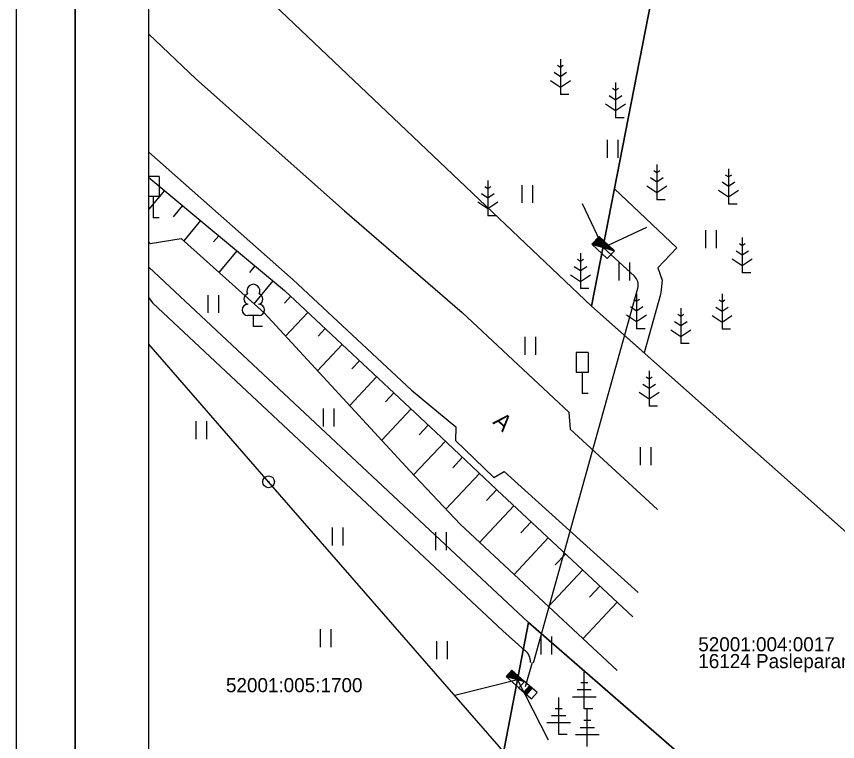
# Model space of a CAD drawing. Extents: x 469361.3 to 469413.8, y 6542171.3 to 6542245.5.
# Drawn here: x 469361.27 to 469396.16, y 6542186.8 to 6542217.59 of the extents above; entities that cross this region are included whole.
import ezdxf

# ---------------------------------------------------------------- set-up
doc = ezdxf.new("R2010")
doc.units = 0
for name, color, linetype in [('HALJASTUS', 7, 'Continuous'), ('Hepta_tarbijatoru', 7, 'Continuous'), ('KASUTUSALA', 7, 'Continuous'), ('KPOHULIIN', 7, 'Continuous'), ('LIIKLUS', 7, 'Continuous'), ('MADALPINGE', 7, 'Continuous'), ('PIIR', 7, 'Continuous'), ('POST', 7, 'Continuous'), ('PUU', 7, 'Continuous'), ('RELJEEF', 7, 'Continuous'), ('TEE', 7, 'Continuous'), ('VORMISTUS', 7, 'Continuous')]:
    doc.layers.add(name, color=color, linetype=linetype)

msp = doc.modelspace()

# ---------------------------------------------------------------- linework, layer by layer
at = {"layer": 'HALJASTUS'}
for p, q in [((469386.366, 6542212.352), (469386.366, 6542211.591)), ((469386.821, 6542212.352), (469386.821, 6542211.591)), ((469382.742, 6542210.432), (469382.742, 6542209.671)), ((469383.197, 6542210.432), (469383.197, 6542209.671)), ((469390.544, 6542208.512), (469390.544, 6542207.751)), ((469390.999, 6542208.512), (469390.999, 6542207.751)), ((469386.863, 6542207.147), (469386.863, 6542206.386)), ((469387.318, 6542207.147), (469387.318, 6542206.386)), ((469369.398, 6542205.761), (469369.398, 6542205)), ((469369.853, 6542205.761), (469369.853, 6542205)), ((469382.87, 6542203.99), (469382.87, 6542203.229)), ((469383.325, 6542203.99), (469383.325, 6542203.229)), ((469374.301, 6542200.94), (469374.301, 6542200.179)), ((469374.756, 6542200.94), (469374.756, 6542200.179)), ((469368.886, 6542200.407), (469368.886, 6542199.646)), ((469369.341, 6542200.407), (469369.341, 6542199.646)), ((469387.773, 6542199.298), (469387.773, 6542198.537)), ((469388.228, 6542199.298), (469388.228, 6542198.537)), ((469374.685, 6542195.885), (469374.685, 6542195.124)), ((469375.14, 6542195.885), (469375.14, 6542195.124)), ((469379.076, 6542195.693), (469379.076, 6542194.932)), ((469379.531, 6542195.693), (469379.531, 6542194.932)), ((469374.173, 6542191.577), (469374.173, 6542190.815)), ((469374.628, 6542191.577), (469374.628, 6542190.815)), ((469383.552, 6542191.257), (469383.552, 6542190.495)), ((469384.007, 6542191.257), (469384.007, 6542190.495)), ((469379.118, 6542191.065), (469379.118, 6542190.304)), ((469379.573, 6542191.065), (469379.573, 6542190.304))]:
    msp.add_line(p, q, dxfattribs=at)
at = {"layer": 'Hepta_tarbijatoru'}
for points in [[(469386.196, 6542207.779), (469385.314, 6542209.631)], [(469386.196, 6542207.779), (469388.057, 6542208.638)], [(469382.553, 6542189.429), (469379.901, 6542188.753)], [(469382.553, 6542189.429), (469383.86, 6542186.881)]]:
    msp.add_lwpolyline(points, dxfattribs=at)
at = {"layer": 'KASUTUSALA'}
msp.add_lwpolyline([(469389.323, 6542207.768), (469388.517, 6542206.919), (469388.699, 6542206.389), (469388.67, 6542205.987), (469388.67, 6542205.985), (469388.67, 6542205.984), (469388.653, 6542205.889), (469388.637, 6542205.794), (469388.636, 6542205.792), (469388.636, 6542205.791), (469387.945, 6542203.307), (469385.71, 6542205.29), (469386.684, 6542210.273)], close=True, dxfattribs=at)
at = {"layer": 'KPOHULIIN'}
msp.add_lwpolyline([(469387.064, 6542180.54), (469371.981, 6542197.833), (469366.891, 6542203.679)], dxfattribs=at)
at = {"layer": 'LIIKLUS'}
for p, q in [((469367.326, 6542210.794), (469366.891, 6542210.794)), ((469367.326, 6542210.794), (469367.326, 6542209.944)), ((469367.326, 6542209.944), (469366.891, 6542209.944)), ((469367.076, 6542209.944), (469367.076, 6542209.044)), ((469367.326, 6542209.044), (469367.076, 6542209.044)), ((469385.055, 6542203.325), (469385.055, 6542202.475)), ((469385.555, 6542203.325), (469385.055, 6542203.325)), ((469385.555, 6542203.325), (469385.555, 6542202.475)), ((469385.555, 6542202.475), (469385.055, 6542202.475)), ((469385.305, 6542202.475), (469385.305, 6542201.575)), ((469385.555, 6542201.575), (469385.305, 6542201.575))]:
    msp.add_line(p, q, dxfattribs=at)
at = {"layer": 'MADALPINGE'}
for p, q in [((469386.024, 6542208.25), (469385.716, 6542207.924)), ((469385.716, 6542207.924), (469386.369, 6542207.307)), ((469385.716, 6542207.924), (469386.677, 6542207.633)), ((469385.727, 6542207.921), (469385.72, 6542207.928)), ((469385.754, 6542207.913), (469385.728, 6542207.937)), ((469385.781, 6542207.904), (469385.737, 6542207.946)), ((469385.808, 6542207.896), (469385.746, 6542207.955)), ((469385.836, 6542207.888), (469385.754, 6542207.965)), ((469385.863, 6542207.88), (469385.763, 6542207.974)), ((469385.89, 6542207.872), (469385.772, 6542207.983)), ((469385.917, 6542207.863), (469385.781, 6542207.992)), ((469385.944, 6542207.855), (469385.789, 6542208.001)), ((469385.971, 6542207.847), (469385.798, 6542208.011)), ((469385.998, 6542207.839), (469385.807, 6542208.02)), ((469386.026, 6542207.83), (469385.815, 6542208.029)), ((469386.053, 6542207.822), (469385.824, 6542208.038)), ((469386.08, 6542207.814), (469385.833, 6542208.047)), ((469386.107, 6542207.806), (469385.841, 6542208.057)), ((469386.134, 6542207.798), (469385.85, 6542208.066)), ((469386.161, 6542207.789), (469385.859, 6542208.075)), ((469386.188, 6542207.781), (469385.868, 6542208.084)), ((469386.216, 6542207.773), (469385.876, 6542208.094)), ((469386.243, 6542207.765), (469385.885, 6542208.103)), ((469386.27, 6542207.757), (469385.894, 6542208.112)), ((469386.297, 6542207.748), (469385.902, 6542208.121)), ((469386.324, 6542207.74), (469385.911, 6542208.13)), ((469386.351, 6542207.732), (469385.92, 6542208.14)), ((469386.378, 6542207.724), (469385.928, 6542208.149)), ((469386.405, 6542207.716), (469385.937, 6542208.158)), ((469386.433, 6542207.707), (469385.946, 6542208.167)), ((469386.46, 6542207.699), (469385.955, 6542208.176)), ((469386.487, 6542207.691), (469385.963, 6542208.186)), ((469386.514, 6542207.683), (469385.972, 6542208.195)), ((469386.541, 6542207.675), (469385.981, 6542208.204)), ((469386.568, 6542207.666), (469385.989, 6542208.213)), ((469386.595, 6542207.658), (469385.998, 6542208.223)), ((469386.623, 6542207.65), (469386.007, 6542208.232)), ((469386.65, 6542207.642), (469386.016, 6542208.241)), ((469386.677, 6542207.633), (469386.024, 6542208.25)), ((469386.369, 6542207.307), (469386.677, 6542207.633)), ((469382.317, 6542189.829), (469382.081, 6542189.561)), ((469382.724, 6542189.39), (469382.277, 6542189.784)), ((469382.746, 6542189.385), (469382.284, 6542189.791)), ((469382.768, 6542189.379), (469382.29, 6542189.799)), ((469382.79, 6542189.373), (469382.297, 6542189.807)), ((469382.811, 6542189.367), (469382.304, 6542189.814)), ((469382.833, 6542189.362), (469382.311, 6542189.822)), ((469382.855, 6542189.356), (469382.317, 6542189.829)), ((469382.081, 6542189.561), (469382.619, 6542189.087)), ((469382.081, 6542189.561), (469382.855, 6542189.356)), ((469382.089, 6542189.558), (469382.083, 6542189.564)), ((469382.111, 6542189.552), (469382.09, 6542189.571)), ((469382.133, 6542189.547), (469382.097, 6542189.579)), ((469382.155, 6542189.541), (469382.103, 6542189.586)), ((469382.177, 6542189.535), (469382.11, 6542189.594)), ((469382.199, 6542189.529), (469382.117, 6542189.602)), ((469382.221, 6542189.524), (469382.123, 6542189.609)), ((469382.243, 6542189.518), (469382.13, 6542189.617)), ((469382.264, 6542189.512), (469382.137, 6542189.624)), ((469382.286, 6542189.506), (469382.143, 6542189.632)), ((469382.308, 6542189.5), (469382.15, 6542189.64)), ((469382.33, 6542189.495), (469382.157, 6542189.647)), ((469382.352, 6542189.489), (469382.163, 6542189.655)), ((469382.374, 6542189.483), (469382.17, 6542189.662)), ((469382.396, 6542189.477), (469382.177, 6542189.67)), ((469382.418, 6542189.471), (469382.184, 6542189.678)), ((469382.439, 6542189.466), (469382.19, 6542189.685)), ((469382.461, 6542189.46), (469382.197, 6542189.693)), ((469382.483, 6542189.454), (469382.204, 6542189.7)), ((469382.505, 6542189.448), (469382.21, 6542189.708)), ((469382.527, 6542189.443), (469382.217, 6542189.715)), ((469382.549, 6542189.437), (469382.224, 6542189.723)), ((469382.571, 6542189.431), (469382.23, 6542189.731)), ((469382.593, 6542189.425), (469382.237, 6542189.738)), ((469382.615, 6542189.419), (469382.244, 6542189.746)), ((469382.636, 6542189.414), (469382.25, 6542189.753)), ((469382.658, 6542189.408), (469382.257, 6542189.761)), ((469382.68, 6542189.402), (469382.264, 6542189.769)), ((469382.702, 6542189.396), (469382.27, 6542189.776)), ((469382.855, 6542189.356), (469382.619, 6542189.087)), ((469382.619, 6542189.087), (469382.855, 6542189.356)), ((469382.619, 6542189.087), (469383.157, 6542188.613)), ((469382.826, 6542188.904), (469383.063, 6542189.173)), ((469383.393, 6542188.882), (469382.855, 6542189.356)), ((469382.985, 6542189.084), (469383.107, 6542188.976)), ((469382.991, 6542189.091), (469383.113, 6542188.983)), ((469382.995, 6542189.096), (469383.118, 6542188.988)), ((469383.001, 6542189.103), (469383.124, 6542188.995)), ((469383.007, 6542189.109), (469383.13, 6542189.002)), ((469383.013, 6542189.116), (469383.135, 6542189.009)), ((469383.018, 6542189.122), (469383.14, 6542189.014)), ((469383.024, 6542189.128), (469383.146, 6542189.021)), ((469383.03, 6542189.135), (469383.152, 6542189.027)), ((469383.036, 6542189.142), (469383.158, 6542189.034)), ((469383.04, 6542189.147), (469383.163, 6542189.04)), ((469383.046, 6542189.154), (469383.169, 6542189.046)), ((469383.052, 6542189.161), (469383.175, 6542189.053)), ((469383.058, 6542189.167), (469383.181, 6542189.06)), ((469382.832, 6542188.911), (469382.955, 6542188.803)), ((469382.838, 6542188.917), (469382.961, 6542188.81)), ((469382.844, 6542188.924), (469382.967, 6542188.817)), ((469382.847, 6542188.927), (469382.969, 6542188.82)), ((469382.853, 6542188.934), (469382.975, 6542188.826)), ((469382.859, 6542188.941), (469382.981, 6542188.833)), ((469382.865, 6542188.948), (469382.987, 6542188.84)), ((469382.871, 6542188.954), (469382.993, 6542188.847)), ((469382.877, 6542188.961), (469382.999, 6542188.853)), ((469382.883, 6542188.968), (469383.005, 6542188.86)), ((469382.889, 6542188.975), (469383.011, 6542188.867)), ((469382.895, 6542188.981), (469383.017, 6542188.874)), ((469382.9, 6542188.988), (469383.023, 6542188.88)), ((469382.905, 6542188.993), (469383.027, 6542188.886)), ((469382.911, 6542189), (469383.033, 6542188.893)), ((469382.917, 6542189.007), (469383.039, 6542188.899)), ((469382.923, 6542189.014), (469383.045, 6542188.906)), ((469382.928, 6542189.019), (469383.05, 6542188.911)), ((469382.934, 6542189.026), (469383.056, 6542188.918)), ((469382.94, 6542189.033), (469383.062, 6542188.925)), ((469382.946, 6542189.039), (469383.068, 6542188.932)), ((469382.949, 6542188.796), (469383.185, 6542189.065)), ((469382.95, 6542189.045), (469383.073, 6542188.937)), ((469382.956, 6542189.051), (469383.079, 6542188.944)), ((469382.962, 6542189.058), (469383.084, 6542188.951)), ((469382.968, 6542189.065), (469383.09, 6542188.957)), ((469382.973, 6542189.07), (469383.095, 6542188.963)), ((469382.979, 6542189.077), (469383.101, 6542188.969)), ((469383.157, 6542188.613), (469383.393, 6542188.882))]:
    msp.add_line(p, q, dxfattribs=at)
for points in [[(469387.528, 6542206.562), (469386.196, 6542207.779)], [(469383.245, 6542190.144), (469387.673, 6542206.059)], [(469366.891, 6542205.649), (469367.055, 6542205.427), (469381.934, 6542191.507), (469382.877, 6542190.671)], [(469383.18, 6542190.157), (469382.891, 6542189.131)]]:
    msp.add_lwpolyline(points, dxfattribs=at)
for centre, radius, start, end in [((469387.191, 6542206.193), 0.5, 344.4513, 47.5946), ((469382.501, 6542190.198), 0.605, 356.4922, 51.474)]:
    msp.add_arc(centre, radius, start, end, dxfattribs=at)
at = {"layer": 'PIIR'}
for points in [[(469366.891, 6542223.149), (469385.71, 6542205.29), (469391.134, 6542233.04)], [(469391.134, 6542233.04), (469385.71, 6542205.29), (469408.141, 6542185.392)], [(469408.141, 6542185.392), (469385.71, 6542205.29), (469366.891, 6542223.149)], [(469366.891, 6542206.95), (469383.02, 6542191.86), (469396.052, 6542180.54)], [(469380.846, 6542180.54), (469383.02, 6542191.86), (469366.891, 6542206.95)], [(469396.052, 6542180.54), (469383.02, 6542191.86), (469380.846, 6542180.54)]]:
    msp.add_lwpolyline(points, dxfattribs=at)
at = {"layer": 'POST'}
for radius in [0.25, 0.0234]:
    msp.add_circle((469371.981, 6542197.833), radius, dxfattribs=at)
at = {"layer": 'PUU'}
for p, q in [((469384.38, 6542215.777), (469384.38, 6542214.277)), ((469384.38, 6542215.427), (469384.255, 6542215.51)), ((469384.504, 6542215.51), (469384.38, 6542215.427)), ((469384.38, 6542215.027), (469384.113, 6542215.205)), ((469384.647, 6542215.205), (469384.38, 6542215.027)), ((469383.956, 6542214.866), (469384.38, 6542214.583)), ((469384.38, 6542214.583), (469384.804, 6542214.866)), ((469386.726, 6542214.793), (469386.726, 6542213.293)), ((469384.74, 6542214.277), (469384.38, 6542214.277)), ((469386.726, 6542214.043), (469386.46, 6542214.221)), ((469386.726, 6542214.443), (469386.602, 6542214.526)), ((469386.851, 6542214.526), (469386.726, 6542214.443)), ((469386.993, 6542214.221), (469386.726, 6542214.043)), ((469386.302, 6542213.882), (469386.726, 6542213.599)), ((469386.726, 6542213.599), (469387.151, 6542213.882)), ((469387.086, 6542213.293), (469386.726, 6542213.293)), ((469388.476, 6542211.308), (469388.476, 6542209.808)), ((469391.527, 6542211.125), (469391.527, 6542209.625)), ((469388.476, 6542210.558), (469388.209, 6542210.736)), ((469388.476, 6542210.958), (469388.351, 6542211.041)), ((469388.6, 6542211.041), (469388.476, 6542210.958)), ((469388.742, 6542210.736), (469388.476, 6542210.558)), ((469391.527, 6542210.775), (469391.402, 6542210.858)), ((469391.651, 6542210.858), (469391.527, 6542210.775)), ((469381.297, 6542210.628), (469381.297, 6542209.128)), ((469388.051, 6542210.398), (469388.476, 6542210.115)), ((469388.476, 6542210.115), (469388.9, 6542210.398)), ((469391.527, 6542210.375), (469391.26, 6542210.552)), ((469391.793, 6542210.552), (469391.527, 6542210.375)), ((469381.297, 6542209.878), (469381.031, 6542210.056)), ((469381.297, 6542210.278), (469381.173, 6542210.361)), ((469381.422, 6542210.361), (469381.297, 6542210.278)), ((469381.564, 6542210.056), (469381.297, 6542209.878)), ((469391.103, 6542210.214), (469391.527, 6542209.931)), ((469391.527, 6542209.931), (469391.951, 6542210.214)), ((469380.873, 6542209.718), (469381.297, 6542209.435)), ((469381.297, 6542209.435), (469381.722, 6542209.718)), ((469388.836, 6542209.808), (469388.476, 6542209.808)), ((469391.887, 6542209.625), (469391.527, 6542209.625)), ((469381.657, 6542209.128), (469381.297, 6542209.128)), ((469392.111, 6542207.853), (469391.987, 6542207.936)), ((469392.111, 6542208.203), (469392.111, 6542206.703)), ((469392.236, 6542207.936), (469392.111, 6542207.853)), ((469392.111, 6542207.453), (469391.845, 6542207.631)), ((469392.378, 6542207.631), (469392.111, 6542207.453)), ((469385.232, 6542207.184), (469385.107, 6542207.267)), ((469385.232, 6542207.534), (469385.232, 6542206.034)), ((469385.356, 6542207.267), (469385.232, 6542207.184)), ((469391.687, 6542207.293), (469392.111, 6542207.01)), ((469392.111, 6542207.01), (469392.535, 6542207.293)), ((469385.232, 6542206.784), (469384.965, 6542206.962)), ((469385.498, 6542206.962), (469385.232, 6542206.784)), ((469384.807, 6542206.623), (469385.232, 6542206.34)), ((469385.232, 6542206.34), (469385.656, 6542206.623)), ((469392.471, 6542206.703), (469392.111, 6542206.703)), ((469385.592, 6542206.034), (469385.232, 6542206.034)), ((469387.62, 6542205.834), (469387.62, 6542204.334)), ((469387.62, 6542205.484), (469387.496, 6542205.567)), ((469387.745, 6542205.567), (469387.62, 6542205.484)), ((469391.249, 6542205.458), (469391.124, 6542205.541)), ((469391.249, 6542205.808), (469391.249, 6542204.308)), ((469391.373, 6542205.541), (469391.249, 6542205.458)), ((469387.62, 6542205.084), (469387.354, 6542205.262)), ((469387.887, 6542205.262), (469387.62, 6542205.084)), ((469389.497, 6542205.201), (469389.497, 6542203.701)), ((469391.249, 6542205.058), (469390.982, 6542205.236)), ((469391.515, 6542205.236), (469391.249, 6542205.058)), ((469371.576, 6542204.895), (469371.096, 6542204.895)), ((469371.336, 6542204.42), (469371.336, 6542204.895)), ((469387.196, 6542204.923), (469387.62, 6542204.641)), ((469387.62, 6542204.641), (469388.045, 6542204.923)), ((469389.497, 6542204.851), (469389.372, 6542204.934)), ((469389.621, 6542204.934), (469389.497, 6542204.851)), ((469390.824, 6542204.898), (469391.249, 6542204.615)), ((469391.249, 6542204.615), (469391.673, 6542204.898)), ((469389.497, 6542204.451), (469389.23, 6542204.628)), ((469389.763, 6542204.628), (469389.497, 6542204.451)), ((469371.716, 6542204.42), (469371.336, 6542204.42)), ((469387.98, 6542204.334), (469387.62, 6542204.334)), ((469389.072, 6542204.29), (469389.497, 6542204.007)), ((469389.497, 6542204.007), (469389.921, 6542204.29)), ((469391.609, 6542204.308), (469391.249, 6542204.308)), ((469389.857, 6542203.701), (469389.497, 6542203.701)), ((469388.153, 6542202.542), (469388.153, 6542201.042)), ((469388.153, 6542202.192), (469388.029, 6542202.275)), ((469388.278, 6542202.275), (469388.153, 6542202.192)), ((469388.153, 6542201.792), (469387.886, 6542201.969)), ((469388.42, 6542201.969), (469388.153, 6542201.792)), ((469387.729, 6542201.631), (469388.153, 6542201.348)), ((469388.153, 6542201.348), (469388.577, 6542201.631)), ((469388.513, 6542201.042), (469388.153, 6542201.042)), ((469385.395, 6542188.194), (469385.395, 6542189.769)), ((469385.545, 6542189.294), (469385.245, 6542189.294)), ((469385.695, 6542188.994), (469385.095, 6542188.994)), ((469384.308, 6542187.096), (469384.308, 6542188.671)), ((469385.895, 6542188.694), (469384.895, 6542188.694)), ((469384.458, 6542188.196), (469384.158, 6542188.196)), ((469385.755, 6542188.194), (469385.395, 6542188.194)), ((469385.525, 6542186.591), (469385.525, 6542188.166)), ((469384.608, 6542187.896), (469384.008, 6542187.896)), ((469385.675, 6542187.691), (469385.375, 6542187.691)), ((469384.808, 6542187.596), (469383.808, 6542187.596)), ((469385.825, 6542187.391), (469385.225, 6542187.391)), ((469384.668, 6542187.096), (469384.308, 6542187.096)), ((469386.025, 6542187.091), (469385.025, 6542187.091))]:
    msp.add_line(p, q, dxfattribs=at)
for centre, radius, start, end in [((469371.336, 6542205.94), 0.277, 332.5799, 207.4201), ((469371.166, 6542205.592), 0.233, 109.0217, 253.1415), ((469371.506, 6542205.592), 0.233, 286.8508, 70.9859), ((469371.098, 6542205.132), 0.238, 90.0016, 269.3953), ((469371.573, 6542205.132), 0.238, 270.6047, 89.9984)]:
    msp.add_arc(centre, radius, start, end, dxfattribs=at)
at = {"layer": 'RELJEEF'}
for p, q in [((469367.558, 6542210.203), (469366.891, 6542209.403)), ((469368.326, 6542209.563), (469367.923, 6542209.079)), ((469369.095, 6542208.923), (469368.375, 6542208.059)), ((469369.863, 6542208.283), (469369.641, 6542208.016)), ((469370.632, 6542207.644), (469369.867, 6542206.725)), ((469371.4, 6542207.004), (469371.164, 6542206.72)), ((469372.169, 6542206.364), (469371.358, 6542205.39)), ((469372.923, 6542205.708), (469372.654, 6542205.42)), ((469373.653, 6542205.025), (469372.706, 6542204.013)), ((469374.384, 6542204.342), (469374.085, 6542204.022)), ((469375.114, 6542203.659), (469374.067, 6542202.54)), ((469375.844, 6542202.975), (469375.515, 6542202.624)), ((469376.574, 6542202.292), (469375.428, 6542201.067)), ((469377.305, 6542201.609), (469376.946, 6542201.225)), ((469378.035, 6542200.926), (469376.789, 6542199.594)), ((469378.765, 6542200.243), (469378.376, 6542199.827)), ((469379.494, 6542199.559), (469378.145, 6542198.13)), ((469380.221, 6542198.872), (469379.805, 6542198.43)), ((469380.949, 6542198.185), (469379.519, 6542196.671)), ((469381.676, 6542197.499), (469381.236, 6542197.033)), ((469382.406, 6542196.816), (469380.949, 6542195.259)), ((469383.136, 6542196.132), (469382.7, 6542195.666)), ((469383.866, 6542195.449), (469382.413, 6542193.895)), ((469384.597, 6542194.766), (469384.161, 6542194.3)), ((469385.327, 6542194.083), (469383.876, 6542192.532)), ((469386.057, 6542193.4), (469385.622, 6542192.935)), ((469386.788, 6542192.717), (469385.339, 6542191.169))]:
    msp.add_line(p, q, dxfattribs=at)
for points in [[(469366.891, 6542210.758), (469372.659, 6542205.955), (469379.321, 6542199.722), (469381.683, 6542197.492), (469387.454, 6542192.094)], [(469366.891, 6542208.012), (469366.955, 6542207.944), (469368.26, 6542208.163), (469371.794, 6542205), (469377.984, 6542198.301), (469380.124, 6542196.027), (469386.793, 6542189.814)]]:
    msp.add_lwpolyline(points, dxfattribs=at)
at = {"layer": 'TEE'}
for points in [[(469366.891, 6542216.837), (469368.893, 6542214.948), (469375.209, 6542209.343), (469380.212, 6542205.014), (469384.737, 6542200.792), (469384.795, 6542200.073), (469388.511, 6542196.655)], [(469366.891, 6542211.832), (469373.024, 6542206.414), (469378.054, 6542201.72), (469379.935, 6542200.169), (469379.92, 6542199.582), (469381.553, 6542198.02), (469381.998, 6542198.266), (469387.691, 6542193.138)]]:
    msp.add_lwpolyline(points, dxfattribs=at)
at = {"layer": 'VORMISTUS'}
for points in [[(469361.266, 6542245.54), (469413.766, 6542245.54), (469413.766, 6542171.29), (469361.266, 6542171.29)], [(469363.766, 6542174.04), (469411.266, 6542174.04), (469411.266, 6542242.79), (469363.766, 6542242.79)], [(469363.766, 6542242.79), (469411.266, 6542242.79), (469411.266, 6542174.04), (469363.766, 6542174.04)], [(469408.141, 6542180.54), (469366.891, 6542180.54), (469366.891, 6542233.04), (469408.141, 6542233.04)]]:
    msp.add_lwpolyline(points, close=True, dxfattribs=at)

# ---------------------------------------------------------------- texts
at = {"layer": 'PIIR'}
for s, p in [('52001:004:0017', (469390.24, 6542190.634)), ('16124 Pasleparanna tee', (469390.24, 6542189.919)), ('52001:005:1700', (469370.17, 6542188.898))]:
    msp.add_text(s, height=0.6, dxfattribs=at).set_placement(p)
at = {"layer": 'TEE'}
msp.add_text('A', height=0.7, rotation=318.1415, dxfattribs=at).set_placement((469381.471, 6542200.332))

doc.saveas('drawing.dxf')
